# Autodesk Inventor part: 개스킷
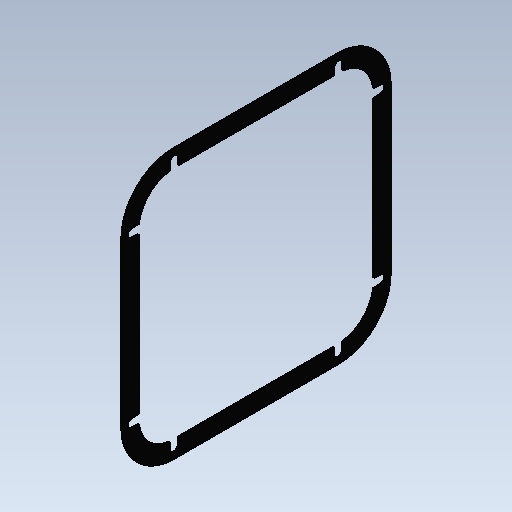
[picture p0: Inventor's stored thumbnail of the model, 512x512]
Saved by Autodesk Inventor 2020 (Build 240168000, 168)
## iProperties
Created: 2022-02
Part Number: 개스킷
Material: 황동, 연질 노란색
Document SubType Name: Modeling
Designer: mdu-edu
Density: 8.47 g/cm^3
Mass: 43.3803 g
Surface Area: 113.92 cm^2
Volume: 5.12165 cm^3
Appearance: 피막 처리 - 검은색
Author: mdu-edu
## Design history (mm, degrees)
sketch "스케치1"
  geometry: L1 (-77, 77)-(77, 77); L2 (77, 77)-(77, -77); L3 (77, -77)-(-77, -77); L4 (-77, -77)-(-77, 77); L5 (-77, 77)-(77, -77); L6 (77, 77)-(-77, -77); 1 further point
  constraints: 12 end point, 2 midpoint, 2 parallel, 2 perpendicular, 1 horizontal
  dimensions: "d1" = 154 distance of L1.end L2.end
extrude "돌출1" new body sketch "스케치1" distance "d2" = 1; taper "d3" = 0 deg
fillet "모깎기1" dims "d4" = 30
sketch "스케치2"
  geometry: L1 (-47, -77)-(47, -77) reference; L2 (77, -47)-(77, 47) reference; L3 (47, 77)-(-47, 77) reference; L4 (-77, 47)-(-77, -47) reference; L5 (67, 47)-(67, -47); L6 (47, -67)-(-47, -67); L7 (-67, -47)-(-67, 47); L8 (-47, 67)-(47, 67); A1 r 30 centre (-47, -47) between (-77, -47) and (-47, -77) reference; A2 r 30 centre (47, -47) between (47, -77) and (77, -47) reference; A3 r 30 centre (47, 47) between (77, 47) and (47, 77) reference; A4 r 30 centre (-47, 47) between (-47, 77) and (-77, 47) reference; A5 r 20 centre (47, 47) between (67, 47) and (47, 67); A6 r 20 centre (47, -47) between (47, -67) and (67, -47); A7 r 20 centre (-47, -47) between (-67, -47) and (-47, -67); A8 r 20 centre (-47, 47) between (-47, 67) and (-67, 47); 1 further point
  constraints: 8 end point, 8 point on circle, 4 centre point, 7 other
  dimensions: "d5" = 10 distance between parallel lines of L2 L5
extrude "돌출2" cut sketch "스케치2" extent not by distance; stored distance "d6" = 1; taper "d7" = 0 deg
sketch "스케치3"
  geometry: L1 (47, 77)-(-47, 77) reference; L2 (77, -47)-(77, 47) reference; L3 (-47, -77)-(47, -77) reference; L4 (-77, 47)-(-77, -47) reference; L5 (-47, 71)-(47, 71); L6 (71, 47)-(71, -47); L7 (47, -71)-(-47, -71); L8 (-71, -47)-(-71, 47); A1 r 30 centre (47, 47) between (77, 47) and (47, 77) reference; A2 r 30 centre (47, -47) between (47, -77) and (77, -47) reference; A3 r 30 centre (-47, -47) between (-77, -47) and (-47, -77) reference; A4 r 30 centre (-47, 47) between (-47, 77) and (-77, 47) reference; A5 r 24 centre (47, 47) between (71, 47) and (47, 71); A6 r 24 centre (47, -47) between (47, -71) and (71, -47); A7 r 24 centre (-47, -47) between (-71, -47) and (-47, -71); A8 r 24 centre (-47, 47) between (-47, 71) and (-71, 47); 9 further points
  constraints: 8 coincident, 8 end point, 8 point on circle, 4 centre point, 7 other
  dimensions: "d8" = 6 distance between parallel lines of L2 L6
hole "구멍1" sketch "스케치3" at (-47, 71), (47, 71), (71, 47), (71, -47), (47, -71), (-47, -71), (-71, -47), (-71, 47) diameter "d9" = 4.5; stored, may be unused: countersink angle "d13" = 90 deg, drill point angle "d15" = 118 deg; dims "d10" = 6, "d11" = 4, "d12" = 2, "d14" = 8
sketch "스케치4"
  geometry: L1 (-47, 67)-(47, 67) reference; L2 (-67, -47)-(-67, 47) reference; L3 (67, 47)-(67, -47) reference; L4 (47, -67)-(-47, -67) reference; L5 (-44.75, 71)-(-44.75, 67); L6 (-49.25, 71)-(-49.25, 66.873); L7 (-71, 49.25)-(-66.873, 49.25); L8 (-71, 44.75)-(-67, 44.75); L9 (0, 0)-(0, 67); L10 (0, 0)-(-67, 0); L11 (49.25, 71)-(49.25, 66.873); L12 (44.75, 71)-(44.75, 67); L13 (71, 49.25)-(66.873, 49.25); L14 (71, 44.75)-(67, 44.75); L15 (-44.75, -71)-(-44.75, -67); L16 (-49.25, -71)-(-49.25, -66.873); L17 (-71, -49.25)-(-66.873, -49.25); L18 (-71, -44.75)-(-67, -44.75); L19 (49.25, -71)-(49.25, -66.873); L20 (44.75, -71)-(44.75, -67); L21 (71, -49.25)-(66.873, -49.25); L22 (71, -44.75)-(67, -44.75); C1 r 2.25 at (47, 71) reference; C2 r 2.25 at (71, 47) reference; C3 r 2.25 at (71, -47) reference; C4 r 2.25 at (47, -71) reference; C5 r 2.25 at (-47, -71) reference; C6 r 2.25 at (-71, -47) reference; A1 r 2.25 centre (-47, 71) between (-44.75, 71) and (-49.25, 71) reference; A2 r 2.25 centre (-71, 47) between (-71, 44.75) and (-71, 49.25) reference; A3 r 20 centre (-47, 47) between (-47, 67) and (-67, 47) reference; A4 r 20 centre (47, 47) between (67, 47) and (47, 67) reference; A5 r 20 centre (47, -47) between (47, -67) and (67, -47) reference; A6 r 20 centre (-47, -47) between (-67, -47) and (-47, -67) reference; A7 r 2.25 centre (-71, 47) between (-71, 49.25) and (-71, 44.75); A8 r 2.25 centre (-47, 71) between (-44.75, 71) and (-49.25, 71)
  constraints: 36 end point, 24 symmetric about line, 10 point on circle, 4 tangent, 2 centre point, 2 coincident, 2 midpoint, 2 perpendicular, 2 point on line, 1 parallel, 1 vertical
extrude "돌출3" cut sketch "스케치4" extent not by distance; stored distance "d16" = 10; taper "d17" = 0 deg
fillet "모깎기2" dims "d18" = 0.5
node "솔리드1"
mirror "대칭1"
mirror "대칭2"
node "투영된 루프1"
